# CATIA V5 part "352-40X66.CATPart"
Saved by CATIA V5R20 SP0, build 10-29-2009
Part number: 352-40X66
Definition: NONE
Nomenclature: 352-40X66
Source: Unknown
Description: 352-40X66
Bounding box of the stored display mesh (mm): x 0 to 66, y -24 to 24, z -24 to 24
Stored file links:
  C:\Users\Utente\Desktop\IO LAVORO\3D X SITO CF\X SITO\PLASTICA\352\352-40X66.CATPart
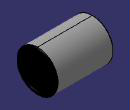
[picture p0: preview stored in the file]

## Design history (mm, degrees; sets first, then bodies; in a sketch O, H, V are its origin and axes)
Body1 "352-40X66" (main body)
  Solid1: solid without history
